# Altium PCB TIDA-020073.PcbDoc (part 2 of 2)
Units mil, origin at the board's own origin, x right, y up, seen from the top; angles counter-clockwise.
Board outline 2125.98 x 2598.43 mil, 4 copper layers (Top Copper, Signal Layer 1, Signal Layer 2, Bottom Copper), stack 62.45 mil thick; 144 components, 83 nets, 376 pads, 155 vias.
Unrouted connection lines stored in the file: 1.
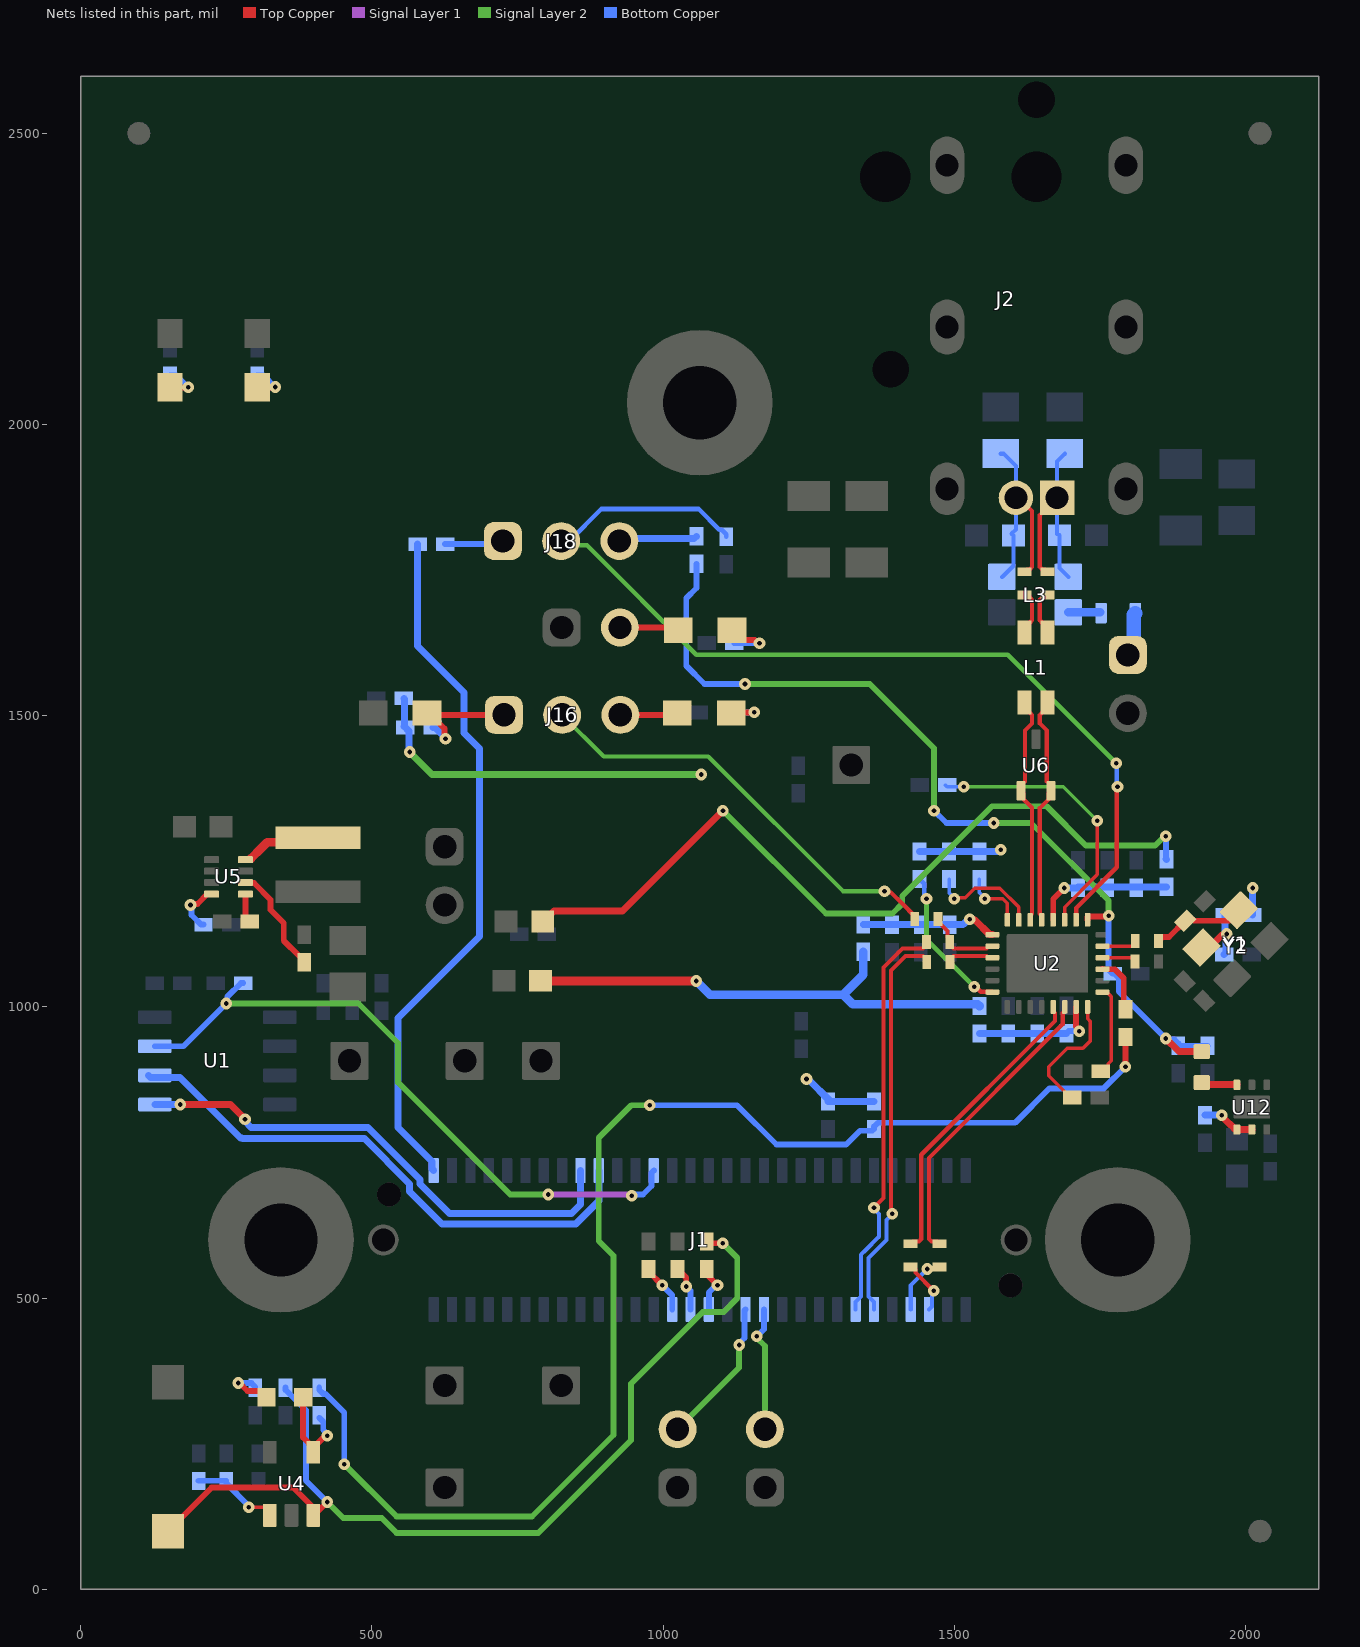
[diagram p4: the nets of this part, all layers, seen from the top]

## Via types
v1: diameter 20, hole 8, Top Copper to Bottom Copper, tented both sides, 137 vias
v2: diameter 19.68, hole 7.87, Top Copper to Bottom Copper, 7 vias
v3: diameter 30, hole 12, Top Copper to Bottom Copper, tented both sides, 5 vias
v4: diameter 24, hole 8, Top Copper to Bottom Copper, tented both sides, 4 vias
v5: diameter 59.06, hole 39.37, Top Copper to Bottom Copper, tented both sides, 2 vias

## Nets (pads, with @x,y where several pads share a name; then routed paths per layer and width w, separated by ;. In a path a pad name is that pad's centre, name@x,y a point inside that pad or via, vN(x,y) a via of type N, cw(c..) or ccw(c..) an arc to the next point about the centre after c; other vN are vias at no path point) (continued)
NetD1_2: D1.2 J16.1 R26.1 | length 216.2
  Top Copper w10: D1.2@594.7,1504.84 597.65,1504.84 D1.2@601,1501.5 ; v1(626.51,1460.32) 624.59,1462.23 624.59,1477.9 D1.2@601,1501.5 ; J16.1@726.78,1501.5 D1.2@601,1501.5
  Bottom Copper w12: R26.1@604.87,1480 608.81,1480 626.51,1462.3 v1(626.51,1460.32)
NetD3_1: D3.1 J16.3 | length 99
  Top Copper w10: J16.3@926.78,1501.5 1021.08,1501.5 D3.1@1024.42,1504.84
NetD3_2: D3.2 R28.2 | length 87.6
  Top Copper w10: D3.2@1116.94,1504.84 1117.9,1505.8 v1(1156.38,1505.8)
  Bottom Copper w10: R28.2@1108.62,1505.65 1108.69,1505.73 1156.31,1505.73 v1(1156.38,1505.8)
NetD4_1: D4.1 J3.2 | length 102.1
  Top Copper w10: J3.2@925.95,1651.55 1021.09,1651.55 D4.1@1025.98,1646.65
NetD4_2: D4.2 R32.2 | length 100.3
  Top Copper w10: D4.2@1118.5,1646.65 1135.16,1630 1157.34,1630 1163.04,1624.3 v1(1165.75,1624.3)
  Bottom Copper w10: R32.2@1122.24,1625 1122.59,1624.65 1165.4,1624.65 v1(1165.75,1624.3)
NetD8_1: D8.1 R62.1 | length 71.7
  Top Copper w10: D8.1@153.35,2063.78 v1(185,2063.78)
  Bottom Copper w10: R62.1@153.35,2084.06 164.72,2084.06 v1(185,2063.78)
NetD9_1: D9.1 R63.1 | length 69.6
  Top Copper w10: D9.1@303.35,2063.78 333.34,2063.78 v1(333.93,2064.37)
  Bottom Copper w10: R63.1@303.35,2084.06 314.25,2084.06 v1(333.93,2064.37)
NetD10_1: D10.1 R65.1 U4.4 | length 171.1
  Top Copper w10: D10.1@382.12,330.07 382.12,260.76 U4.4@399.58,243.3 ; U4.4@399.58,235.43 U4.4@399.58,243.3 ; v1(423.62,263.97) 421.71,262.06 418.33,262.06 U4.4@399.58,243.3
  Bottom Copper w10: R65.1@409.68,294.81 416.49,288 416.49,273.81 423.62,266.68 v1(423.62,263.97)
NetD10_2: D10.2 R36.2 | length 92.2
  Top Copper w10: v1(270.42,354.32) 273.13,354.32 286.63,340.82 308.38,340.82 D10.2@319.13,330.07
  Bottom Copper w10: v1(270.42,354.32) 293.19,354.32 300,347.5 R36.2@300,346.49
NetJ1_30: J1.30 R10.1 | length 1202.8
  Bottom Copper w12: R10.1@578.68,1794.68 578.68,1619.77 658.56,1539.89 658.56,1470.06 685,1443.62 685,1120.9 545,980.9 545,793.39 603.45,734.95 603.45,722.15 J1.30@606.31,719.29
NetJ1_42: J1.42 J4.2 | length 216.6
  Signal Layer 2 w10: v1(1161.01,434.52) 1161.01,431.81 1175,417.82 J4.2@1175,275
  Bottom Copper w10: v1(1161.01,434.52) 1173.24,446.75 J1.42@1173.24,480.71
NetJ1_43: J1.43 J5.2 | length 254.1
  Signal Layer 2 w10: J5.2@1025,275 1130.59,380.59 v1(1130.59,419.69)
  Bottom Copper w10: v1(1130.59,419.69) 1130.59,422.4 1140.01,431.82 1140.01,478.98 J1.43@1141.74,480.71
NetJ1_45: J1.45 R7.2 | length 84.7
  Top Copper w10: R7.2@1075,550 1075,540.6 v1(1093.55,522.05)
  Bottom Copper w10: J1.45@1078.75,480.71 1078.75,510 1090.8,522.05 v1(1093.55,522.05)
NetJ1_46: J1.46 R8.2 | length 78.5
  Top Copper w10: R8.2@1025,550 1040,535 v1(1040,520)
  Bottom Copper w10: v1(1040,520) 1047.25,512.75 J1.46@1047.25,480.71
NetJ1_47: J1.47 R9.2 | length 86.2
  Top Copper w10: R9.2@975,550 975,545.67 v1(998.62,522.05)
  Bottom Copper w10: v1(998.62,522.05) 1015.76,504.91 J1.47@1015.76,480.71
NetJ6_1: J6.1 R16.2 | length 77.3
  Bottom Copper w25: J6.1@1798.11,1604.46 1808.46,1614.81 1808.46,1673.67 R16.2@1811.12,1676.32
NetJ16_2: J16.2 R5.1 | length 753.2
  Top Copper w7.15: v1(1380.16,1198.82) 1382.62,1196.36 1391.7,1196.36 1410.89,1177.17 1432.26,1155.8 R5.1@1432.26,1151.3
  Signal Layer 2 w7.15: J16.2@826.78,1501.5 898.28,1430 1077.63,1430 1308.81,1198.82 v1(1380.16,1198.82)
NetJ18_3: J18.3 R11.1 | length 135.6
  Bottom Copper w12: J18.3@925,1800 929.02,1804.02 1053.25,1804.02 R11.1@1057.27,1808.05
NetL2_1: L2.1 U5.4 | length 129.9
  Top Copper w15: U5.4@292.53,1254.99 309.88,1272.35 320.49,1282.95 399.71,1282.95 L2.1@407.57,1290.81
NetL3_2: L3.2 R16.1 | length 56.6
  Bottom Copper w10: R16.1@1750.87,1677.52 R16.1@1752.06,1676.32
  Bottom Copper w15: L3.2@1695.92,1677.52 R16.1@1750.87,1677.52
NetL4_2: L4.2 R13.2 | length 1385.8
  Top Copper w12: L4.2@788.54,1146.65 794.44,1146.65 812.47,1164.68 930.42,1164.68 v1(1102.85,1337.11)
  Signal Layer 2 w10: v1(1102.85,1337.11) 1279.66,1160.3 1394.01,1160.3 1410.89,1177.17 1410.89,1190.49 1564.98,1344.58 1658.66,1344.58 1725.97,1277.27 1844.94,1277.27 1861,1293.33 v1(1863.16,1293.33)
  Bottom Copper w10: R13.2@1863.72,1253.95 v1@1863.72,1292.77
  Bottom Copper w12: v1(1863.16,1293.33) v1@1863.72,1292.77 ; R13.2@1863.72,1253.95 R13.2@1864.28,1253.39
NetL6_1: L6.1 U12.6 | length 63.1
  Top Copper w12: L6.1@1922.17,867.2 U12.6@1985.31,867.2
NetR18_1: R18.1 U5.2 | length 181.7
  Top Copper w10: U5.2@283.04,1213.57 283.94,1212.67 297.62,1212.67 326.23,1184.06 326.23,1166.92 348.86,1144.3 348.86,1113.87 375.25,1087.47 377.23,1087.47 381.06,1083.64 R18.1@381.06,1081.67
NetR20_2: R20.2 U5.8 | length 89.3
  Top Copper w10: v1(188.56,1175) 190.47,1176.91 200.51,1176.91 217.49,1193.89 U5.8@224.77,1193.89
  Bottom Copper w10: v1(188.56,1175) 190.47,1173.09 190.47,1158.06 207.18,1141.35 R20.2@211.11,1141.35
NetR25_2: R25.2 U5.1 | length 50.9
  Top Copper w10: U5.1@283.04,1193.89 283.04,1153.46 289.85,1146.65 R25.2@290.66,1146.65
NetR38_2: R38.2 R68.2 U4.1 | length 153.4
  Top Copper w6: v1(288.79,141.28) 315.96,141.28 324.77,132.47 U4.1@324.77,127.16
  Bottom Copper w10: R68.2@202.66,186.67 249.36,186.67 R38.2@250,186.03 250,182.09 288.79,143.3 v1(288.79,141.28)
NetR43_1: R43.1 U2.9 | length 155.7
  Top Copper w6: R43.1@1751.65,889.8 1755.59,889.8 1764.4,898.61 1764.4,902.55 1769.29,907.44 1769.29,1017.96 1761.61,1025.64 U2.9@1754.53,1025.64
NetR44_1: R44.1 U2.8 | length 222.2
  Top Copper w6: R44.1@1702.86,844.71 1698.93,844.71 1662.03,881.6 1662.03,897.26 1694.02,929.25 1721.02,929.25 1733.91,942.14 1733.91,974.7 1728.94,979.68 U2.8@1728.94,1000.05
NetR45_1: R45.1 U2.11 | length 97.7
  Top Copper w10: U2.11@1754.53,1065.01 1754.8,1064.73 1775.54,1064.73 1791,1049.27 1791,998.79 R45.1@1793.98,995.81
NetR46_1: R46.1 U2.17 | length 479.3
  Top Copper w6: U2.17@1689.57,1149.66 1689.57,1171.54 1745.51,1227.49 v1(1745.51,1319.65)
  Signal Layer 2 w6: v1(1516.38,1378.25) 1686.91,1378.25 v1(1745.51,1319.65)
  Bottom Copper w6: R46.1@1484.83,1381.03 1487.6,1378.25 v1(1516.38,1378.25)
NetR72_1: R72.1 U12.1 U12.2 | length 91.8
  Top Copper w12: v1(1959.45,814.2) 1959.45,812.6 1967.5,804.55 1967.5,804.48 1975.68,796.3 1975.75,796.3 1982.45,789.59 U12.1@1985.41,789.59 U12.2@2011,789.59
  Bottom Copper w12: R72.1@1930.41,814.2 v1(1959.45,814.2)
RESET: R41.1 R45.2 R65.2 | length 2289.9
  Top Copper w10: v1@1793.95,897.49 R45.2@1793.95,948.55
  Signal Layer 2 w10: v1(452.58,215) 542.58,125 775,125 915,265 915,572.92 889.77,598.15 889.77,775.51 945.65,831.39 v1(977.16,831.39)
  Bottom Copper w10: R65.2@409.68,346.49 409.68,342.55 416.49,335.74 420.43,335.74 452.58,303.58 v1(452.58,215) ; v1(977.16,831.39) 1127.17,831.39 1194.74,763.83 1314.39,763.83 1338.05,787.49 R41.1@1359.12,787.49 ; R41.1@1362.21,790.58 1362.21,794.52 1369.02,801.33 1604.57,801.33 1663.47,860.22 1756.68,860.22 v1(1793.93,897.47)
RESET_N: R7.1 R64.1 S1.1 U4.3 | length 1652.3
  Top Copper w10: S1.1@150,100 225,175 365,175 399.8,140.2 U4.3@399.8,126.18 ; U4.3@399.8,125 U4.3@399.8,126.18 ; v1(423.62,150) U4.3@399.8,126.18 ; R7.1@1075,594.29 v1(1102.56,594.29)
  Signal Layer 2 w10: v1(423.62,150) 451.08,122.54 517.04,122.54 542.58,97 785.86,97 945,256.14 945,353.2 1068.14,476.34 1104.11,476.34 1127.51,499.74 1127.51,569.34 v1(1102.56,594.29)
  Bottom Copper w10: R64.1@352,346.49 352,342.55 386.87,307.68 386.87,186.76 v1(423.62,150)
RX_CLK: R34.2 U2.28 | length 258.9
  Top Copper w8: v1(1534.31,1034.48) 1537.56,1034.48 1545.68,1026.36 1564.83,1026.36 U2.28@1565.55,1025.64
  Signal Layer 2 w8: v1(1452.26,1186.04) 1452.26,1116.56 v1(1534.31,1034.48)
  Bottom Copper w8: R34.2@1440.53,1219.6 1448.35,1211.79 1448.35,1193.2 1452.26,1189.28 v1(1452.26,1186.04)
RX_CTRL: R22.2 U2.22 | length 107.8
  Top Copper w6: v1(1552.2,1186.04) 1582.95,1186.04 1586.05,1182.93 1591.14,1177.85 U2.22@1591.14,1149.66
  Bottom Copper w6: R22.2@1543.32,1219.6 1543.32,1196.02 1552.2,1187.14 v1(1552.2,1186.04)
RX_ER: R24.2 U2.21 | length 190.9
  Top Copper w6: v1(1500.01,1186.04) 1501.73,1187.76 1519.01,1187.76 1535.16,1203.91 1548.64,1203.91 1548.77,1204.04 1578.39,1204.04 1610.83,1171.6 U2.21@1610.83,1149.66
  Bottom Copper w6: R24.2@1491.05,1219.6 1491.05,1196.02 1500.01,1187.06 v1(1500.01,1186.04)
RX_N: C27.1 J1.37 | length 708.7
  Top Copper w7.15: v1(1362.21,655) 1362.21,655.89 1378.29,671.96 1378.29,1067.8 1385.99,1075.51 1403.45,1092.96 1411.15,1100.66 1446.5,1100.66 1452.49,1106.65 C27.1@1452.49,1111.15
  Bottom Copper w7.15: J1.37@1330.72,480.71 1330.72,493.5 1339.89,502.68 1339.89,574.66 1347.59,582.37 1370.83,605.61 1370.83,644.39 1362.21,653 v1(1362.21,655)
RX_P: C26.1 J1.36 | length 681.8
  Top Copper w7.15: v1(1393.71,645) 1391.44,647.27 1391.44,1062.36 1416.6,1087.51 1446.63,1087.51 1452.61,1081.53 C26.1@1452.61,1077.03
  Bottom Copper w7.15: J1.36@1362.21,480.71 1362.21,493.5 1353.04,502.68 1353.04,569.22 1383.98,600.16 1383.98,634.39 1393.71,644.11 v1(1393.71,645)
RXP_N: C27.2 R5.2 U2.24 | length 118.5
  Top Copper w7.15: R5.2@1472.26,1151.3 1472.26,1146.8 1488.56,1130.5 1488.56,1119.57 1492.49,1115.65 C27.2@1492.49,1111.15 1492.49,1106.65 1498.47,1100.66 U2.24@1555.5,1100.66
RXP_P: C26.2 U2.25 | length 69.9
  Top Copper w7.15: C26.2@1492.61,1077.03 1492.61,1081.53 1498.6,1087.51 U2.25@1555.5,1087.51
SCL: J1.21 U1.6 | length 954.9
  Bottom Copper w12: U1.6@116.34,882.52 119.73,879.14 170.79,879.14 274.74,775.19 276.84,775.19 278.15,773.88 487.32,773.88 565,696.2 565,683.48 620.81,627.67 850.21,627.67 889.77,667.23 J1.21@889.77,719.29
SDA: J1.22 U1.5 | length 875.7
  Top Copper w12: v1(170.79,832.52) 257.13,832.52 v1(282.19,807.46)
  Bottom Copper w12: U1.5@127.37,832.52 v1(170.79,832.52) ; v1@282.19,803.89 292.9,793.19 493.46,793.19 583,703.65 583,696.26 633.59,645.67 842.75,645.67 858.28,661.19 J1.22@858.28,719.29
TRD1_N: L1.4 U2.20 U6.1 | length 395.9
  Top Copper w7.15: L1.4@1620.67,1522.61 1620.67,1513.75 1628.91,1505.51 1629.59,1505.51 1633.78,1501.33 1633.78,1486.62 1621.78,1474.62 1621.78,1387.03 1614.76,1380.01 U6.1@1614.76,1371.16 1619.06,1366.86 1619.06,1356.72 1633.78,1342.01 1633.78,1160.01 1630.51,1156.74 U2.20@1630.51,1149.66
TRD1_P: L1.1 U2.19 U6.2 | length 395.9
  Top Copper w7.15: U2.19@1650.2,1149.66 1650.2,1156.74 1646.93,1160.01 1646.93,1341.59 1661.65,1356.31 1661.65,1366.86 U6.2@1665.94,1371.16 1665.94,1380.01 1658.93,1387.03 1658.93,1474.62 1646.93,1486.62 1646.93,1501.33 1651.12,1505.51 1651.8,1505.51 1660.04,1513.75 L1.1@1660.04,1522.61
TRD2_N: C36.2 L1.3 | length 78.8
  Top Copper w7.15: L1.3@1620.67,1642.69 1620.67,1651.55 1628.91,1659.78 1629.59,1659.78 1633.78,1663.97 1633.78,1699.21 1629.59,1703.4 1624.59,1703.4 C36.2@1620.67,1707.32
TRD2_P: C37.2 L1.2 | length 78.8
  Top Copper w7.15: L1.2@1660.04,1642.69 1660.04,1651.55 1651.8,1659.78 1651.12,1659.78 1646.93,1663.97 1646.93,1699.21 1651.12,1703.4 1656.11,1703.4 C37.2@1660.04,1707.32
TRD3_N: C36.1 D5.1 J2.2 L3.4 R54.2 | length 384.2
  Top Copper w7.15: J2.2@1605.81,1874.38 1612.52,1874.38 1612.52,1872.61 1633.78,1851.35 1633.78,1755.44 1629.59,1751.25 1624.59,1751.25 C36.1@1620.67,1747.32
  Bottom Copper w7.15: R54.2@1580,1950 1584.38,1950 1605.81,1928.57 J2.2@1605.81,1874.38 1605.81,1820.06 D5.1@1598.34,1812.6 ; L3.4@1581.75,1738.54 1582.5,1738.54 1601.57,1757.6 D5.1@1601.57,1809.37
TRD3_P: C37.1 D6.2 J2.1 L3.1 R53.2 | length 368.7
  Top Copper w7.15: C37.1@1660.04,1747.32 1656.11,1751.25 1651.12,1751.25 1646.93,1755.44 1646.93,1844.64 J2.1@1676.67,1874.38
  Bottom Copper w7.15: D6.2@1676.67,1812.19 J2.1@1676.67,1874.38 1676.67,1936.67 R53.2@1690,1950 ; D6.2@1680.93,1810 1680.93,1753.53 L3.1@1695.92,1738.54
TX_N: C29.2 U2.6 | length 516.6
  Top Copper w7.15: C29.2@1475,593.62 1471.07,597.55 1460.76,597.55 1456.57,601.74 1456.57,740.75 1686.3,970.47 1686.3,989.69 1689.57,992.96 U2.6@1689.57,1000.05
TX_P: C28.2 U2.5 | length 516.6
  Top Copper w7.15: C28.2@1425,593.62 1428.93,597.55 1439.24,597.55 1443.43,601.74 1443.43,746.2 1673.15,975.92 1673.15,989.69 1669.88,992.96 U2.5@1669.88,1000.05
TXC_N: C29.1 J1.34 | length 103.9
  Top Copper w7.15: v1(1453.62,550) 1455.43,551.81 1473.19,551.81 C29.1@1475,553.62
  Bottom Copper w7.15: J1.34@1425.2,480.71 1425.2,521.58 v1(1453.62,550)
TXC_P: C28.1 J1.33 | length 95.8
  Top Copper w7.15: C28.1@1425,553.62 1429.5,553.62 1433.43,549.7 1433.43,543.93 1464.6,512.75 v1(1465,512.75)
  Bottom Copper w7.15: J1.33@1456.7,480.71 1461.98,485.99 1461.98,506.26 1465,509.27 v1(1465,512.75)
V_GND: C56.2 R19.2 R21.1 Y1.4 Y2.4 | length 125.1
  Top Copper w12: Y1.4@1924.49,1102.16 1925.89,1103.55 1927.49,1101.95 1937.83,1101.95 1959.59,1123.71 1966.38,1123.71 v1(1967.91,1125.24)
  Bottom Copper w12: C56.2@1963.43,1090.4 1966.38,1093.35 1966.38,1123.71 v1(1967.91,1125.24) 1967.91,1127.41 1964.67,1130.65 R21.1@1964.67,1157.96
VDDp7: C9.1 C14.2 C19.1 R15.1 U2.7 | length 206.4
  Top Copper w10: v1@1709.25,966.59 U2.7@1709.25,1000.05
  Bottom Copper w10: C14.2@1692.63,954.59 C14.2@1692.88,954.84 1696.64,958.59 v1(1714.54,958.59)
  Bottom Copper w12: R15.1@1543.31,954.34 1543.56,954.59 1592.91,954.59 1642.6,954.59 C14.2@1692.63,954.59
VDDp18: C7.1 C12.2 C17.1 R13.1 U2.18 | length 238.8
  Top Copper w10: U2.18@1669.88,1149.66 1669.88,1185.43 v1(1688.74,1204.28)
  Bottom Copper w12: v1(1688.74,1204.28) 1688.82,1204.36 1710.75,1204.36 1712.54,1206.15 R13.1@1864.28,1206.15
VDDp23: C8.1 C13.2 C18.1 R14.1 U2.23 | length 236.5
  Top Copper w12: v1(1526.5,1150.76) 1528.03,1149.23 1535.85,1149.23 1561.02,1124.06 U2.23@1565.55,1124.06
  Bottom Copper w12: R14.1@1343.78,1141.83 1393.13,1141.83 1442.49,1141.83 1492.44,1141.83 1515.4,1141.83 1524.34,1150.76 v1(1526.5,1150.76)
Vpu33: L5.2 R14.2 R15.2 R21.2 R22.1 R24.1 R26.2 R27.1 R34.1 R39.2 R41.2 | length 1845.5
  Top Copper w15: L5.2@789.88,1044.87 790.05,1044.7 1057.11,1044.7 v1(1057.27,1044.53)
  Signal Layer 2 w12: v1(565,1437.76) 603.53,1399.23 v1(1065.48,1399.23)
  Bottom Copper w12: R27.1@554.87,1530 R27.1@556.25,1528.62 ; R26.2@557.62,1480 556.25,1481.38 R27.1@556.25,1528.62 ; v1(565,1437.76) 563.47,1439.29 563.47,1474.19 556.28,1481.38 554.87,1481.38 556.25,1482.76 R27.1@556.25,1528.62 ; v1@1244.89,874.85 v1(1246.42,876.38) 1247.96,874.85 1250.39,874.85 R39.2@1285.44,839.79 ; R39.2@1283.47,837.82 R41.2@1362.21,837.82 ; R34.1@1440.53,1266.85 R24.1@1491.05,1266.85 1574.68,1266.85 1577.84,1270.01 v1(1580,1270.01) ; R21.2@2011.92,1157.96 2012.19,1158.23 2012.19,1204.01 v1(2012.46,1204.28)
  Bottom Copper w15: v1(1057.27,1044.53) 1080.77,1021.04 1309.52,1021.04 ; R14.2@1343.78,1094.58 1343.78,1055.3 1309.52,1021.04 ; R15.2@1543.31,1001.58 1540.06,1004.83 1325.72,1004.83 1309.52,1021.04
Vsleep: C51.1 C52.1 C54.1 L6.2 R11.2 U2.15 | length 1609.3
  Top Copper w10: U2.15@1728.94,1149.66 1728.94,1153.94 1730.21,1155.21 1763.56,1155.21 v1(1765.09,1156.74)
  Top Copper w12: v1(1863.16,945.96) 1885.7,923.43 L6.2@1925,923.43
  Signal Layer 2 w10: v1(1140.8,1554.46) 1354.93,1554.46 1465.31,1444.08 v1(1465.31,1337.11) ; v1(1567.92,1315.83) 1631.93,1315.83 1765.09,1182.67 v1(1765.09,1156.74)
  Bottom Copper w10: R11.2@1057.27,1760.8 1057.27,1719.41 1039.76,1701.9 1039.76,1585.82 1071.12,1554.46 v1(1140.8,1554.46) ; v1@1465,1337.53 1486.7,1315.83 v1(1567.92,1315.83) ; v1(1765.09,1156.74) 1765.09,1063.88 C54.1@1771.88,1057.09 1775.82,1057.09 1782.63,1050.28 1782.63,1026.5 v1(1863.16,945.96) 1865.87,945.96 1867.86,943.96 1878,943.96 1884.81,937.15 C52.1@1884.81,933.22 C51.1@1934.81,933.22
WAKE: J18.2 R12.2 U2.16 | length 1738.7
  Top Copper w8: U2.16@1709.25,1149.66 1709.25,1169.89 1779.04,1239.68 1779.04,1377.06 v1(1780.23,1378.25)
  Signal Layer 2 w8: J18.2@825,1800 832.21,1792.79 869.48,1792.79 1057.27,1605 1591.54,1605 1726.54,1470 v1(1778.21,1418.33)
  Bottom Copper w8: J18.2@825,1800 838.66,1800 893.66,1855 1061,1855 1096.87,1819.13 1100.81,1819.13 1108.62,1811.32 R12.2@1108.62,1807.38 ; v1(1778.21,1418.33) 1779.22,1417.32 1779.22,1379.26 v1(1780.23,1378.25)
WAKE_N: J18.1 R10.2 | length 101.3
  Bottom Copper w10: R10.2@625.93,1794.68 719.68,1794.68 J18.1@725,1800
WP: J1.18 R4.1 U1.7 | length 1144.9
  Signal Layer 1 w10: v1(802.99,677.95) 944.57,677.95 v1(946.54,675.98)
  Signal Layer 2 w10: v1(250,1005.95) 477.11,1005.95 545,938.06 545,870.55 737.6,677.95 v1(802.99,677.95) v1@803.64,677.95
  Bottom Copper w10: U1.7@127.37,932.52 176.57,932.52 v1(250,1005.95) 251.91,1007.86 251.91,1017.62 275.19,1040.89 R4.1@279.12,1040.89 ; v1(946.54,675.98) 948.45,677.89 965.8,677.89 980.4,692.49 980.4,715.43 J1.18@984.26,719.29
XI: R17.1 U2.13 | length 62.9
  Top Copper w6: U2.13@1754.53,1104.38 1806.17,1104.38 1810.91,1109.13 R17.1@1810.91,1113.63
XO: R78.1 U2.12 | length 59.8
  Top Copper w6: U2.12@1754.53,1084.69 1806.06,1084.69 1810.56,1080.19 R78.1@1810.56,1078.28
XO_comb: C30.1 R17.2 Y1.3 Y2.3 | length 154.2
  Top Copper w10: R17.2@1851.58,1113.63 1858.05,1120.1 1868.77,1120.1 C30.1@1896.65,1147.98 ; C30.1@1899.43,1150.76 1909.06,1150.76 1911.85,1147.98 1972.38,1147.98 1980.28,1155.88 Y2.3@1989.92,1155.88
pads on no net: FID1.1 FID2.1 FID3.1 FID4.1 FID5.1 FID6.1 H2.1 H3.1 H4.1 J1. J1.2 J1.3 J1.5 J1.6 J1.8 J1.9 J1.19 J1.24 J1.25 J1.31 J1.39 J1.40 J1.52 J1.53 J1.58 J1.59 J2.MH1 J2.MH2 J2.MH3 J2.MH4 LBL1.0 SH-J1.0 SH-J2.0 SH-J3.0 SH-J4.0 SH-J5.0 SH-J6.0 SH-J8.0 U2.1 U2.2 U2.3 U2.4 U2.10 U2.26 U2.27 U12.5

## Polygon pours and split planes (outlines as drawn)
+3V3_REG on Top Copper "TOP_COPPER_+3V3_REG_P004" (solid, remove dead copper, pour order 4): 333.93,1216.6 333.93,1172.26 372.23,1133.96 372.23,1112.16 389.86,1094.53 640,1094.53 675,1129.53 675,1182.07 603.21,1253.86 514.82,1253.86 481.69,1220.73 337.49,1220.73
GND on Top Copper "TOP_COPPER_GND_P015" (solid, remove dead copper, pour order 15): 2125.98,1805.82 1159.79,1805.82 1159.79,2550.82 0,2550.82 0,0 2125.98,0
GND_PHY on Top Copper "TOP_COPPER_GND_PHY_P012" (solid, pour order 12): 1185,2550 2075,2550 2075,1825 1425.39,1825 1185,1825
+3V3_REG on Signal Layer 2 "SIGNAL_LAYER_2_+3V3_REG_P007" (solid, remove dead copper, pour order 7): 502.57,1362.26 502.94,1160.56 565,1098.5 565,831.75 777.28,831.75 777.28,1362.26
GND on Signal Layer 2 "SIGNAL_LAYER_2_GND_P013" (solid, pour order 13): 1595,724.68 1590.82,728.86 1293.31,728.86 1293.31,454.31 1337.43,410.2 1554.45,410.2 1596.46,452.21 1595,453.67
Vpu33 on Signal Layer 2 "SIGNAL_LAYER_2_VPU33_P006" (solid, remove dead copper, pour order 6): 1028.06,1430 2027.61,1430 2027.61,837.82 1027.38,837.82
GND on Signal Layer 1 "SIGNAL_LAYER_1_GND_P008" (solid, pour order 8): 0,2550 1190,2550 1190,1810 2125.98,1810 2125.98,0 0.01,0
GND on Bottom Copper "BOTTOM_COPPER_GND_P009" (solid, remove dead copper, pour order 9): 0,2560 1170,2560 1170,1845.7 2125.98,1845.7 2125.98,0 0,0

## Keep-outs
Keep-Out Layer:
  text ".Layer_Name" at 577,-858.49 h60

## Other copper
Top Copper:
  pour cut-out: 322.92,1328.17 322.92,1220.73 491.83,1220.73 491.15,1328.17
  pour cut-out: 1575,1930 1550.94,1905.94 1550.94,1443.13 1550.94,1225.14 1602.94,1173.15 1691.69,1173.15 1721.35,1202.81 1721.35,1441.93 1721.35,1910.88 1702.11,1930.12 1574.74,1930.12
  pour cut-out: 1555.5,1109.57 1524.07,1141.01 1408.7,1141.01 1350.4,1082.71 1350.4,840.97 1350.4,700.14 1325.26,675 1325.26,636.31 1360.12,601.45 1403.35,601.45 1428.65,626.76 1428.65,873.44 1428.65,1046.62 1530.02,1046.62 1555.5,1072.1
  pour cut-out: 1642.6,989.69 1642.6,983.09 1424.19,764.69 1424.19,649.76 1393.71,619.28 1393.71,527.17 1436.21,484.67 1500.59,484.67 1507.38,491.46 1507.38,626.37 1482.51,651.24 1482.51,729.5 1704.41,951.4 1704.41,989.69
  text ".Layer_Name" at 577,-858.49 h60
Bottom Copper:
  pour cut-out: 1425,573.62 1425,534.81 1405.19,515 1405.19,460.86 1421.05,445 1467.49,445 1475.9,453.4 1475.9,502.06 1495.5,521.67 1495.5,553.12 1475,573.62
  pour cut-out: 1335,675 1335,624.89 1315.37,605.26 1315.37,455.09 1319.61,450.86 1369.12,450.86 1381.41,463.15 1381.41,525.7 1393.71,538 1393.71,578.8 1423.14,608.23 1423.14,670.23 1411.64,681.73 1341.05,681.73 1334.32,675
  text ".Layer_Name" at 577,-858.49 h60

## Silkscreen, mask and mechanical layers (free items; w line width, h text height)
Top Overlay:
  text "This document can handle board shapes up to 7.9in x 10in, although" at -66.54,5651.38 h60
  text "our panel vendors top out at 7in x 10in." at -66.54,5527.32 h60
  text "To re-size the board shape, do the following:" at -11.54,5403.26 h60
  text "Select lines on M1 Board Outline and delete (easy in single layer mode...shift+s)" at 48.46,5279.2 h60
  text "Draw a rectangle using lines (example will be for a 4\" x 6\" board" at 48.46,5155.14 h60
  text "Enter Place Line mode (keyboard pl)" at 258.46,5031.08 h60
  text "keyboard jo to jump to origin, hit enter" at 258.46,4907.02 h60
  text "keyboard jl to jump to location, set x to 6000, hit enter twice" at 258.46,4782.97 h60
  text "keyboard jl to jump to location, set x to 6000 and y to 4000, hit enter twice" at 258.46,4658.91 h60
  text "keyboard jl to jump to location, set x to 0 and y to 4000, hit enter twice" at 258.46,4534.85 h60
  text "keyboard jo to jump to origin, hit enter" at 258.46,4410.79 h60
  text "Hit ESC twice to exit place line mode" at 258.46,4286.73 h60
  text "Select lines on M1 Board Outline" at 48.46,4142.68 h60
  text "Menu Design|Board Shape|Define from Selected Objects (keyboard dsd)" at 48.46,4038.61 h60
  text "If you re-size the board, don't forget to move the drill table strings on the" at -66.54,3719.38 h60
  text "Drill Drawing Layer...they should be just to the right of your board shape" at 126.46,3613.38 h60
  text "5V0" at 93.24,2233 h40
  text "3V3" at 245.8,2233 h40
  text "SoC/Wake/Vsleep" at 73,1791.33 h40
  text "LED_1" at 474.8,1639.66 h40
  text "PoDL" at 1874.2,1569.14 h30
  text "Master/Slave" at 200.72,1564.81 h40
  text "12V" at 1874.2,1519.75 h30
  text "3V3" at 582,1360.47 h30
  text "/" at 2011.39,1150.97 h40 r315
  text "Reset" at 89.32,408.24 h30
  text "MDC" at 1134.79,353.65 h30
  text "MDIO" at 972.07,352.5 h30
  text "SoC" at 1241,261.74 h30
  text "SoC" at 881.09,256 h30
  text "'.PRJ_Number'" at 1364.5,200.65 h108.27
  text "PHY" at 881,156 h30
  text "PHY" at 1241.95,150.32 h30
  text "Rev: .PCB_Rev" at 1370.09,97 h108.27
  text ".Layer_Name" at 577,-858.49 h60
Bottom Overlay:
  lines w5: 1564.23,1190.5 1588.72,1190.5
  text "/" at 1987.62,1020.68 h40
  text ".Layer_Name" at 577,-858.49 h60
Top Paste:
  text ".Layer_Name" at 577,-858.49 h60
Bottom Paste:
  text ".Layer_Name" at 577,-858.49 h60
Top Mask:
  text ".Layer_Name" at 577,-858.49 h60
  text ".Layer_Name" at 577,-858.49 h60
Bottom Mask:
  text ".Layer_Name" at 577,-858.49 h60
Drill Guide:
  text ".Layer_Name" at 577,-858.49 h60
M1 Board Outline:
  the board outline again, w5
  text ".Layer_Name" at 577,-858.49 h60
M2 Board Dimensions:
  rectangle: 0,-275 125,-150
  rectangle: 125,-400 500,-275
  lines w7: 0,-275 1000,-275 ; 125,-400 125,-150 ; 250,-400 250,-150 ; 500,-400 500,-150 ; 750,-400 750,-150 ; 0,-400 1000,-400 1000,-150 0,-150 0,-400
  text ".Layer_Name" at 577,-858.49 h60
M3 3D STEP Top:
  text ".Layer_Name" at 577,-858.49 h60
M4 3D STEP Bottom:
  text ".Layer_Name" at 577,-858.49 h60
M5 Assembly Top:
  lines w10: -292,-930.17 6308,-930.17 ; -292,-726.83 6310,-726.83 ; -292,-523.5 -292,-1133.5 3713,-1133.5 6310,-1133.5 6310,-523.5 -291.5,-523.5 -291.5,-1133.5 1284,-1133.5 ; 2173,-1133.5 2173,-523.5 ; 3440,-726.83 3440,-523.5 ; 4280,-726.83 4280,-523.5 ; 4902,-1140 4902,-937.17
  text "COMPONENTS MARKED 'DNP' SHOULD NOT BE POPULATED." at 1153.5,-318.5 h60
  text "ASSEMBLY VARIANT:" at 1153,-434 h60
  text ".VariantName" at 2189,-434 h60
  text "PCB VIEWED FROM TOP SIDE" at -228.5,-655.67 h60
  text "BOARD #:" at 2248,-655.67 h60
  text ".PRJ_Number" at 2793.5,-655.67 h60
  text "REV:" at 3638,-655.67 h60
  text ".PCB_Rev" at 3929.5,-655.67 h60
  text "SVN REV:" at 4476,-655.67 h60
  text ".VersionControl_RevNumber" at 4982,-655.67 h60
  text "TID #:" at 2248,-859 h60
  text ".TID" at 2793.5,-859 h60
  text "PLOT NAME =" at -228.5,-1064.34 h60
  text ".plot_File_Name" at 577,-1064.34 h60
  text "GENERATED    :" at 2250,-1064.34 h60
  text ".Print_Date" at 3119.5,-1064.34 h60
  text ".Print_Time" at 3848.5,-1064.34 h60
  text "TEXAS INSTRUMENTS" at 5113,-1064.34 h60
M6 Assembly Bottom:
  lines w10: -292.5,-727.33 6309.5,-727.33 ; -290.5,-930.67 6309.5,-930.67 ; 1115.5,-1140.5 1115.5,-937.67 ; 1737.5,-727.33 1737.5,-524 ; 2577.5,-727.33 2577.5,-524 ; 3844.5,-1134 3844.5,-524 ; 4733.5,-1134 6309,-1134 6309,-524 -292.5,-524 -292.5,-1134 2304.5,-1134 6309.5,-1134 6309.5,-524
  text "COMPONENTS MARKED 'DNP' SHOULD NOT BE POPULATED." at 6102,-318 h60
  text ".VariantName" at 5058,-434 h60
  text "ASSEMBLY VARIANT:" at 6097,-434 h60
  text ".VersionControl_RevNumber" at 1035.5,-656.17 h60
  text "SVN REV:" at 1541.5,-656.17 h60
  text ".PCB_Rev" at 2088,-656.17 h60
  text "REV:" at 2379.5,-656.17 h60
  text ".PRJ_Number" at 3224,-656.17 h60
  text "BOARD #:" at 3769.5,-656.17 h60
  text "PCB VIEWED FROM BOTTOM SIDE" at 6246,-656.17 h60
  text ".TID" at 3224,-859.5 h60
  text "TID #:" at 3769.5,-859.5 h60
  text "TEXAS INSTRUMENTS" at 904.5,-1064.84 h60
  text ".Print_Time" at 2169,-1064.84 h60
  text ".Print_Date" at 2898,-1064.84 h60
  text "GENERATED    :" at 3767.5,-1064.84 h60
  text ".plot_File_Name" at 5440.5,-1064.84 h60
  text "PLOT NAME =" at 6246,-1064.84 h60
M9 Title Sheet:
  drawing of 57 lines, arcs and shapes, not listed
  text "1" at 739.84,8036.5 h70
  text "2" at 3235.5,8036.5 h70
  text "3" at 5724.84,8036.5 h70
  text "4" at 8231.51,8036.5 h70
  text "5" at 10730.5,8036.5 h70
  text "6" at 13235.5,8036.5 h70
  text "A" at -416.5,6893.5 h70
  text "A" at 14383.5,6893.5 h70
  text "B" at -416.5,4513.5 h70
  text "B" at 14383.5,4513.5 h70
  text "C" at -416.5,2138.5 h70
  text "C" at 14383.5,2138.5 h70
  text "PROJECT TITLE:" at 11343.5,277.5 h45
  text ".PRJ_Title" at 11393.5,144.17 h70
  text "DESIGNED FOR:" at 11343.5,-23.5 h45
  text ".PRJ_Customer" at 11393.5,-163.5 h70
  text "D" at -416.5,-231.5 h70
  text "D" at 14383.5,-231.5 h70
  text "FILE NAME:" at 11343.5,-323.5 h45
  text ".PCB_File_Name_No_Path" at 11393.5,-443.5 h70
  text "Texas Instruments (TI) and/or its licensors do not warrant the accuracy or completeness of this specification" at 6374,-605.34 h45
  text "ENGINEER:" at 11343.5,-613.5 h45
  text "LAYOUT BY:" at 12848.5,-613.5 h45
  text "or any information contained therein. TI and/or its licensors do not warrant that this design will meet" at 6329.01,-718 h45
  text ".PRJ_Engineer" at 11393.5,-768.49 h70
  text ".PCB_Layout" at 12899,-768.49 h70
  text "the specifications, will be suitable for your application or fit for any particular purpose, or will operate in" at 6329.01,-830.67 h45
  text ".Layer_Name" at 577,-858.49 h60
  text "ALTIUM DESIGNER VERSION:" at 12848.5,-923.5 h45
  text "an implementation. TI and/or its licensors do not warrant that the design is production worthy. You should" at 6329.01,-943.33 h45
  text "completely validate and test your design implementation to confirm the system functionality for your application." at 6374,-1056 h45
  text ".print_Scale" at 11393.5,-1056.83 h70
  text ".Application_BuildNumber" at 12899,-1056.83 h70
  text "1" at 739.84,-1263.5 h70
  text "2" at 3235.5,-1263.5 h70
  text "3" at 5724.84,-1263.5 h70
  text "4" at 8231.51,-1263.5 h70
  text "5" at 10730.5,-1263.5 h70
  text "6" at 13235.5,-1263.5 h70
M10 Fab Notes:
  drawing of 189 lines, arcs and shapes, not listed
  text "DESIGN INFORMATION" at 12382.02,6356.17 h60
  text "MIN. TRACK WIDTH:" at 11737.46,6224.05 h60
  text "8" at 12833.7,6224.05 h60
  text "MIL" at 12988.46,6224.05 h60
  text "MIN. CLEARANCE:" at 11737.46,6099.92 h60
  text "0.2" at 12773.7,6099.93 h60
  text "mm" at 12988.46,6099.92 h60
  text "MIN. VIA PAD SIZE:" at 11737.46,5975.8 h60
  text "24" at 12803.71,5975.8 h60
  text "MIL" at 12988.46,5975.8 h60
  text "0.05mm (2MIL)" at 12432.46,5845.9 h60
  text "MINIMUM ANNULAR RING" at 11408.23,5837.67 h60
  text "EXTERNAL" at 13140.46,5837.67 h60
  text "PER" at 11608.23,5727.55 h60
  text "IPC-D-275 CLASS 2 LEVEL C" at 11828.23,5727.54 h60
  text "MIL, HOLES" at 13316.46,5627.07 h60
  text "+/-" at 12924,5618.48 h60
  text "+/-" at 13778,5618.48 h60
  text "REGISTRATION TOLERANCES:" at 11408.23,5617.42 h60
  text "METAL" at 12608,5617.42 h60
  text "5" at 13184.2,5617.42 h60
  text "3" at 14017.2,5617.42 h60
  text "MIL" at 14133.46,5617.42 h60
  text "HOLE SIZE TOLERANCE (UNLESS OTHERWISE SPECIFIED):" at 11408.23,5519.1 h60
  text "+/-" at 13778,5516.23 h60
  text "3" at 14017.2,5515.17 h60
  text "MIL" at 14133.46,5515.17 h60
  text "MATERIAL:" at 11333.46,5377.52 h60
  text "FR-4 High Tg" at 12319.9,5249 h60
  text "X" at 12175.46,5241.01 h60
  text "FR-408" at 11754.46,5236.49 h60
  text "OTHER" at 13242.46,5236.49 h60
  text "62 MIL (1.6mm) +/-10%" at 12074.56,5093.46 h60
  text "X" at 11954.46,5091.01 h60
  text "THICKNESS:" at 11408.23,5085.24 h60
  text "OTHER" at 13359.46,5085.24 h60
  text "TOLERANCE:" at 11408.23,4946.92 h60
  text "X" at 12256.46,4946.92 h60
  text "ANSI IPC-6012 TYPE 3 CLASS 2" at 12434.48,4946.92 h60
  text "OTHER +/-" at 12434.46,4802.73 h60
  text "BOW & TWIST:" at 11408.23,4657.54 h60
  text "X" at 12256.46,4657.54 h60
  text "ANSI IPC-6012 TYPE 3 CLASS 2" at 12434.48,4657.54 h60
  text "OTHER +/-" at 12434.46,4510.85 h60
  text "DRILLING:" at 11333.46,4380.23 h60
  text "NC_DRILL FILES" at 13094.46,4275.04 h60
  text "REFERENCE:" at 11408.23,4271.1 h60
  text "X" at 12065.46,4271.01 h60
  text "AS SHOWN" at 12243.46,4271.1 h60
  text "X" at 12966.46,4271.1 h60
  text "OTHER" at 13392.46,4128.85 h60
  text "PTH COPPER THICKNESS:" at 11407.91,4125.32 h60
  text "X" at 12547.14,4125.32 h60
  text "20-30 um" at 12675.14,4125.32 h60
  text "BOARD FINISH:" at 11333.46,3977.73 h60
  text "SILKSCREEN:" at 11488.68,3867.6 h60
  text "X" at 12446.46,3867.6 h60
  text "TOP" at 12563.46,3867.6 h60
  text "X" at 12956.46,3867.6 h60
  text "BOTTOM" at 13074.46,3867.6 h60
  text "SILKSCREEN COLOR:" at 11488.68,3712.41 h60
  text "X" at 12445.46,3712.41 h60
  text "WHITE" at 12563.46,3712.41 h60
  text "OTHER" at 13074.46,3712.41 h60
  text "X" at 12576.46,3568.96 h60
  text "GREEN" at 12694.46,3568.96 h60
  text "OTHER" at 13312.46,3568.96 h60
  text "SOLDER RESIST COLOR:" at 11488.68,3562.1 h60
  text "X" at 12576.46,3414.71 h60
  text "MATTE" at 12694.46,3414.71 h60
  text "SEMI-GLOSS" at 13312,3414.07 h60
  text "IMMERSION GOLD (ENIG)" at 12394.46,3241.94 h60
  text "ENEPIG" at 13732,3234.72 h60
  text "SURFACE FINISH:" at 11333.46,3233.72 h60
  text "X" at 12216.46,3233.72 h60
  text "IMM. TIN/SILVER OR EQUIV" at 11663,3096.4 h60
  text "OTHER" at 13094.46,3092.47 h60
  text "ARRAY/PANEL:" at 11333.46,2937.09 h60
  text "CUT AND TRIM PER M1 BOARD OUTLINE" at 12394.46,2928.87 h60
  text "N.C. ROUTE" at 12394.46,2792.9 h60
  text "X" at 13082.46,2792.9 h60
  text "V. SCORE" at 13260.46,2792.9 h60
  text "CERTIFICATION:" at 11333.46,2663.77 h60
  text "MATERIALS AND WORKMANSHIP FOR ALL PCBS" at 12058.46,2663.77 h60
  text "TO MEET OR EXCEED THE REQUIREMENTS OF:" at 12058.46,2569.71 h60
  text "X" at 11695.97,2441.08 h60
  text "ANSI IPC-A-600F CLASS ->" at 11823.96,2441.08 h60
  text "X" at 13471.97,2441.08 h60
  text "2" at 13581.96,2441.08 h60
  text "1" at 13266.96,2439.58 h60
  text "3" at 13935.96,2439.58 h60
  text "X" at 12507.97,2293.39 h60
  text "RoHS" at 12635.96,2293.39 h60
  text "OTHER" at 13280.36,2293.39 h60
  text "PER ORDER" at 13677.42,2293.39 h60
  text "ALL BOARDS MUST MEET OR EXCEED UL94-V0 REQUIREMENTS." at 11361,2139.57 h60
  text "PCB MUST BEAR THE UL94V-0 UL REGISTERED MATERIAL ID NUMBER" at 11361,2023.5 h60
  text "ADDITIONAL REQUIREMENTS:" at 11333.46,1854.08 h60
  text "MICROSECTION:" at 11408.23,1746.95 h60
  text "YES" at 12313.96,1746.95 h60
  text "REQUIRED" at 13175.46,1602.62 h60
  text "BARE BOARD ELEC. TEST:" at 11408.23,1599.76 h60
  text "NONE" at 12713.96,1599.76 h60
  text "X" at 13057.46,1599.76 h60
  text "PER ORDER" at 13767.46,1599.76 h60
  text "XX MIL VIAS REQUIRE NON-CONDUCTIVE FILL AND PLANARIZE" at 11576.38,1394.82 h59
  text "XX MIL VIAS REQUIRE CONDUCTIVE FILL AND PLANARIZE" at 11584.38,1290.84 h60
  text "OUTER XX MIL TRACES REQUIRE 50 OHM SINGLE-ENDED IMPEDANCE" at 11583.39,1127.46 h58
  text "LAYER 2 & 3 (INNER LAYERS) XX MIL WIDE, XX MIL SPACE / TRACES REQUIRE 100 OHM DIFFERENTIAL IMPEDANCE" at 11575.39,891.74 h60
  text ".Layer_Name" at 577,-858.49 h60
M11 Gerber Information:
  lines w10: -292,-930.17 6308,-930.17 ; -292,-726.83 6310,-726.83 ; -292,-523.5 -292,-1133.5 3713,-1133.5 6310,-1133.5 6310,-523.5 -291.5,-523.5 -291.5,-1133.5 1284,-1133.5 ; 2173,-1133.5 2173,-523.5 ; 3440,-726.83 3440,-523.5 ; 4280,-726.83 4280,-523.5 ; 4902,-1140 4902,-937.17
  text "ALL ARTWORK VIEWED FROM TOP SIDE" at -228.5,-655.67 h60
  text "BOARD #:" at 2248,-655.67 h60
  text ".PRJ_Number" at 2793.5,-655.67 h60
  text "REV:" at 3638,-655.67 h60
  text ".PCB_Rev" at 3929.5,-655.67 h60
  text "SVN REV:" at 4476,-655.67 h60
  text ".VersionControl_RevNumber" at 4982,-655.67 h60
  text "LAYER NAME =" at -228.5,-858.49 h60
  text "TID #:" at 2248,-859 h60
  text ".TID" at 2793.5,-859 h60
  text "PLOT NAME =" at -228.5,-1064.34 h60
  text ".plot_File_Name" at 577,-1064.34 h60
  text "GENERATED    :" at 2250,-1064.34 h60
  text ".Print_Date" at 3119.5,-1064.34 h60
  text ".Print_Time" at 3848.5,-1064.34 h60
  text "TEXAS INSTRUMENTS" at 5113,-1064.34 h60
M12 Stackup:
  drawing of 295 lines, arcs and shapes, not listed
  text "Board Layer Stack" at 7110.3,10185 h60
  text "Constant" at 7680.16,10185 h60
  text "Thickness" at 8330,10185 h60
  text "Material" at 9189.77,10185 h60
  text "Name" at 10129.51,10185 h60
  text "Layer" at 10539.42,10185 h60
  text "Top Overlay" at 10129.51,10065 h60
  text "3.8" at 7680.16,9945 h60
  text "0.59mil" at 8330,9945 h60
  text "Solder Resist" at 9189.77,9945 h60
  text "Top Mask" at 10129.51,9945 h60
  text "1.38mil" at 8330,9825 h60
  text "Top Copper" at 10129.51,9825 h60
  text "1" at 10539.42,9825 h60
  text "4.6" at 7680.16,9705 h60
  text "8.28mil" at 8330,9705 h60
  text "7628" at 9189.77,9705 h60
  text "Dielectric 1" at 10129.51,9705 h60
  text "0.60mil" at 8330,9585 h60
  text "Signal Layer 1" at 10129.51,9585 h60
  text "2" at 10539.42,9585 h60
  text "4.5" at 7680.16,9465 h60
  text "41.93mil" at 8330,9465 h60
  text "FR-4" at 9189.77,9465 h60
  text "Core" at 10129.51,9465 h60
  text "0.60mil" at 8330,9345 h60
  text "Signal Layer 2" at 10129.51,9345 h60
  text "3" at 10539.42,9345 h60
  text "4.6" at 7680.16,9225 h60
  text "8.28mil" at 8330,9225 h60
  text "7628" at 9189.77,9225 h60
  text "Dielectric 2" at 10129.51,9225 h60
  text "1.38mil" at 8330,9105 h60
  text "Bottom Copper" at 10129.51,9105 h60
  text "4" at 10539.42,9105 h60
  text "3.8" at 7680.16,8985 h60
  text "0.59mil" at 8330,8985 h60
  text "Solder Resist" at 9189.77,8985 h60
  text "Bottom Mask" at 10129.51,8985 h60
  text "Bottom Overlay" at 10129.51,8865 h60
  text ".Layer_Name" at 577,-858.49 h60
M13 Component Bodies Top:
  text ".Layer_Name" at 577,-858.49 h60
M14 Component Bodies Bottom:
  text ".Layer_Name" at 577,-858.49 h60
M15 Courtyards Top:
  text ".Layer_Name" at 577,-858.49 h60
M16 Courtyards Bottom:
  text ".Layer_Name" at 577,-858.49 h60
Drill Drawing:
  circle w10: c10528.66,6112.24 r27.56
  circle w10: c10528.66,5740.16 r16.54
  circle w10: c10528.66,5740.16 r27.56
  lines w10: 10501.1,5836.63 10556.22,5836.63 10556.22,5891.75 10501.1,5891.75 10501.1,5836.63 ; 10501.1,5988.22 10528.66,5960.65 10556.22,5988.22 10528.66,6015.78 10501.1,5988.22 ; 10501.1,6222.49 10514.88,6236.27 10501.1,6250.05 10514.88,6250.05 10528.66,6263.83 10542.44,6250.05 10556.22,6250.05 10542.44,6236.27 10556.22,6222.49 10542.44,6222.49 10528.66,6208.71 10514.88,6222.49 10501.1,6222.49 ; 10501.1,6332.73 10501.1,6346.52 10514.88,6360.3 10501.1,6374.08 10501.1,6387.86 10514.88,6387.86 10528.66,6374.08 10542.44,6387.86 10556.22,6387.86 10556.22,6374.08 10542.44,6360.3 10556.22,6346.52 10556.22,6332.73 10542.44,6332.73 10528.66,6346.52 10514.88,6332.73 10501.1,6332.73 ; 10501.1,6456.76 10528.66,6470.54 10556.22,6456.76 10542.44,6484.32 10556.22,6511.88 10528.66,6498.1 10501.1,6511.88 10514.88,6484.32 10501.1,6456.76 ; 10501.1,6594.57 10514.88,6608.35 10501.1,6622.13 10514.88,6622.13 10528.66,6635.91 10542.44,6622.13 10556.22,6622.13 10542.44,6608.35 10556.22,6594.57 10542.44,6594.57 10528.66,6580.79 10514.88,6594.57 10501.1,6594.57 ; 10501.1,6759.94 10528.66,6704.81 10556.22,6759.94 10501.1,6759.94 ; 10501.1,6842.62 10501.1,6870.18 10514.88,6870.18 10514.88,6883.96 10542.44,6883.96 10542.44,6870.18 10556.22,6870.18 10556.22,6842.62 10542.44,6842.62 10542.44,6828.84 10514.88,6828.84 10514.88,6842.62 10501.1,6842.62 ; 10501.1,6952.87 10528.66,6966.65 10556.22,6952.87 10542.44,6980.43 10556.22,7007.99 10528.66,6994.21 10501.1,7007.99 10514.88,6980.43 10501.1,6952.87 ; 10501.1,7090.68 10501.1,7118.24 10514.88,7118.24 10514.88,7132.02 10542.44,7132.02 10542.44,7118.24 10556.22,7118.24 10556.22,7090.68 10542.44,7090.68 10542.44,7076.89 10514.88,7076.89 10514.88,7090.68 10501.1,7090.68 ; 10512.12,5847.65 10545.2,5847.65 10545.2,5880.73 10512.12,5880.73 10512.12,5847.65 ; 10512.12,6467.79 10528.66,6476.05 10545.2,6467.79 10536.93,6484.32 10545.2,6500.86 10528.66,6492.59 10512.12,6500.86 10520.39,6484.32 10512.12,6467.79 ; 10512.12,6600.08 10520.39,6608.35 10512.12,6616.62 10520.39,6616.62 10528.66,6624.89 10536.93,6616.62 10545.2,6616.62 10536.93,6608.35 10545.2,6600.08 10536.93,6600.08 10528.66,6591.81 10520.39,6600.08 10512.12,6600.08 ; 10512.12,6748.91 10528.66,6715.84 10545.2,6748.91 10512.12,6748.91 ; 10512.12,7096.19 10512.12,7112.72 10520.39,7112.72 10520.39,7120.99 10536.93,7120.99 10536.93,7112.72 10545.2,7112.72 10545.2,7096.19 10536.93,7096.19 10536.93,7087.92 10520.39,7087.92 10520.39,7096.19 10512.12,7096.19
  lines w12: 7290.32,5675.39 10606.2,5675.39 ; 7290.32,7163.71 10606.2,7163.71 ; 7856.12,5551.37 7856.12,7287.74 ; 8667.74,5551.37 8667.74,7287.74 ; 9042.49,5551.37 9042.49,7287.74 ; 9301.29,5551.37 9301.29,7287.74 ; 9937.15,5551.37 9937.15,7287.74 ; 10268.84,5551.37 10268.84,7287.74 ; 7290.32,5551.37 10606.2,5551.37 10606.2,7287.74 7290.32,7287.74 7290.32,5551.37
  text "Hole Tolerance" at 7818.91,7200.92 h72
  text "Drill Layer Pair" at 8630.54,7200.92 h72
  text "Hole Type" at 9005.29,7200.92 h72
  text "Plated" at 9264.08,7200.92 h72
  text "Finished Hole Size" at 9899.94,7200.92 h72
  text "Quantity" at 10231.63,7200.92 h72
  text "Symbol" at 10531.79,7200.92 h72
  text "Top Copper - Bottom Copper" at 8630.54,7076.89 h60
  text "Round" at 9005.29,7076.89 h60
  text "NPTH" at 9264.08,7076.89 h60
  text "41.34mil (1.050mm)" at 9899.94,7076.89 h60
  text "2" at 10231.63,7076.89 h60
  text "Top Copper - Bottom Copper" at 8630.54,6952.87 h60
  text "Round" at 9005.29,6952.87 h60
  text "NPTH" at 9264.08,6952.87 h60
  text "62.99mil (1.600mm)" at 9899.94,6952.87 h60
  text "2" at 10231.63,6952.87 h60
  text "Top Copper - Bottom Copper" at 8630.54,6828.84 h60
  text "Round" at 9005.29,6828.84 h60
  text "NPTH" at 9264.08,6828.84 h60
  text "86.61mil (2.200mm)" at 9899.94,6828.84 h60
  text "2" at 10231.63,6828.84 h60
  text "Top Copper - Bottom Copper" at 8630.54,6704.81 h60
  text "Round" at 9005.29,6704.81 h60
  text "PTH" at 9264.08,6704.81 h60
  text "7.87mil (0.200mm)" at 9899.94,6704.81 h60
  text "7" at 10231.63,6704.81 h60
  text "Top Copper - Bottom Copper" at 8630.54,6580.79 h60
  text "Round" at 9005.29,6580.79 h60
  text "PTH" at 9264.08,6580.79 h60
  text "8.00mil (0.203mm)" at 9899.94,6580.79 h60
  text "141" at 10231.63,6580.79 h60
  text "Top Copper - Bottom Copper" at 8630.54,6456.76 h60
  text "Round" at 9005.29,6456.76 h60
  text "PTH" at 9264.08,6456.76 h60
  text "12.00mil (0.305mm)" at 9899.94,6456.76 h60
  text "5" at 10231.63,6456.76 h60
  text "Top Copper - Bottom Copper" at 8630.54,6332.73 h60
  text "Round" at 9005.29,6332.73 h60
  text "PTH" at 9264.08,6332.73 h60
  text "39.37mil (1.000mm)" at 9899.94,6332.73 h60
  text "6" at 10231.63,6332.73 h60
  text "Top Copper - Bottom Copper" at 8630.54,6208.71 h60
  text "Round" at 9005.29,6208.71 h60
  text "PTH" at 9264.08,6208.71 h60
  text "40.00mil (1.016mm)" at 9899.94,6208.71 h60
  text "23" at 10231.63,6208.71 h60
  text "Top Copper - Bottom Copper" at 8630.54,6084.68 h60
  text "Round" at 9005.29,6084.68 h60
  text "PTH" at 9264.08,6084.68 h60
  text "125.98mil (3.200mm)" at 9899.94,6084.68 h60
  text "3" at 10231.63,6084.68 h60
  text "Top Copper - Bottom Copper" at 8630.54,5960.65 h60
  text "Slot" at 9005.28,5960.65 h60
  text "PTH" at 9264.08,5960.65 h60
  text "39.37mil (1.000mm)" at 9899.94,5960.65 h60
  text "2" at 10231.63,5960.65 h60
  text "Top Copper - Bottom Copper" at 8630.54,5836.63 h60
  text "Slot" at 9005.28,5836.63 h60
  text "PTH" at 9264.08,5836.63 h60
  text "39.37mil (1.000mm)" at 9899.94,5836.63 h60
  text "2" at 10231.63,5836.63 h60
  text "Top Copper - Bottom Copper" at 8630.54,5712.6 h60
  text "Slot" at 9005.28,5712.6 h60
  text "PTH" at 9264.08,5712.6 h60
  text "39.37mil (1.000mm)" at 9899.94,5712.6 h60
  text "2" at 10231.63,5712.6 h60
  text "197 Total" at 10231.63,5588.57 h60
  text "= Calculated from tool start centre position to tool end centre position." at 9543.99,5501.76 h60
  text "Routed Path Length" at 10082.35,5501.76 h60
  text "Slot definitions :" at 10531.79,5501.76 h60
  text "= Routed Path Length + Tool Size = Slot length as defined in the PCB layout" at 9743.29,5452.14 h60
  text "Hole Length" at 10082.35,5452.14 h60
  text ".Layer_Name" at 577,-858.49 h60
M17 Embedded Cavity:
  text ".Layer_Name" at 577,-858.49 h60
M18 Embedded Assembly:
  text ".Layer_Name" at 577,-858.49 h60
M19 Embedded Keepout:
  text ".Layer_Name" at 577,-858.49 h60

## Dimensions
0,-400 to 1000,-400 on M2 Board Dimensions
0,0 to 0,2598.43 on M2 Board Dimensions
0,0 to 2125.98,0 on M2 Board Dimensions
